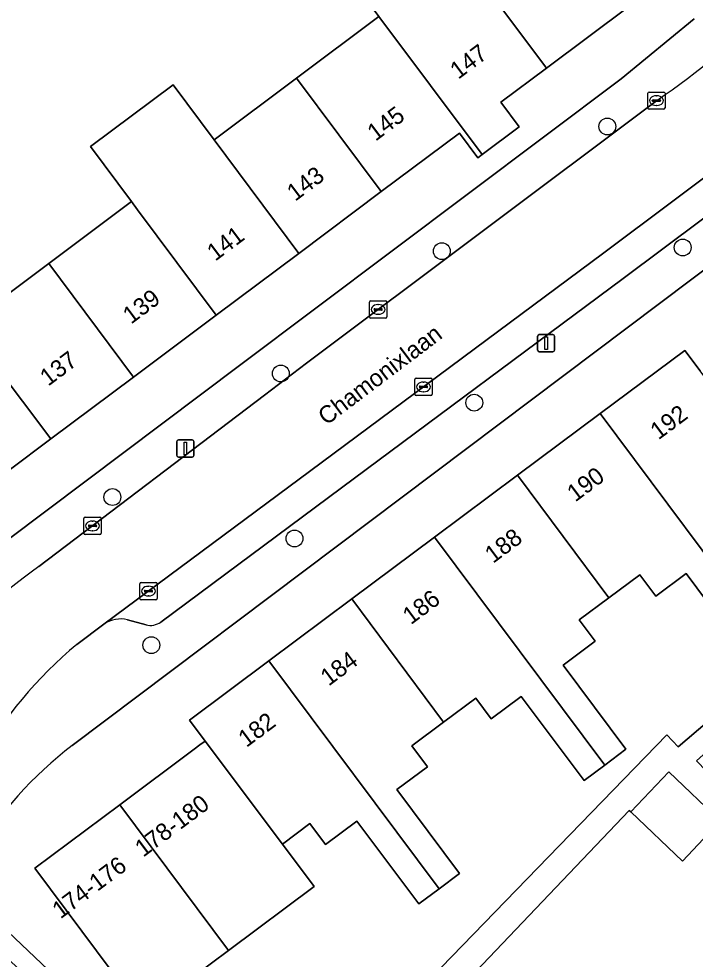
# Model space of a CAD drawing. Extents: x 158472 to 159562, y 388525 to 389606.
# Drawn here: x 159054.8 to 159094.1, y 388835.8 to 388890.5 of the extents above; entities that cross this region are included whole.
import ezdxf

# ---------------------------------------------------------------- set-up
doc = ezdxf.new("R2010")
doc.units = 0
for name, color, linetype in [('IMGEO_Boom', 7, 'Continuous'), ('IMGEO_Erf', 7, 'Continuous'), ('IMGEO_Kolk', 7, 'Continuous'), ('IMGEO_Lichtmast', 7, 'Continuous'), ('IMGEO_Openbare_ruimte_label', 7, 'Continuous'), ('IMGEO_Pand', 7, 'Continuous'), ('IMGEO_Pand_nummerreeks', 7, 'Continuous'), ('IMGEO_Parkeervlak_open', 7, 'Continuous'), ('IMGEO_Rijbaan_lokaal_open', 7, 'Continuous'), ('IMGEO_Voetpad_open', 7, 'Continuous')]:
    doc.layers.add(name, color=color, linetype=linetype)

msp = doc.modelspace()

# ---------------------------------------------------------------- linework, layer by layer
at = {"layer": 'IMGEO_Boom'}
for centre in [(159089.041, 388884.212), (159079.43, 388876.966), (159093.422, 388877.175), (159070.073, 388869.861), (159081.31, 388868.163), (159060.285, 388862.679), (159070.861, 388860.269), (159062.548, 388854.072)]:
    msp.add_circle(centre, 0.489, dxfattribs=at)
at = {"layer": 'IMGEO_Erf'}
for points in [[(159105.034, 388905.658), (159102.901, 388908.014), (159102.46, 388908.501), (159100.858, 388907.302), (159102.997, 388904.443), (159098.122, 388900.795), (159093.382, 388897.248), (159094.272, 388896.059), (159094.191, 388895.998), (159089.429, 388892.434), (159090.34, 388891.218), (159085.501, 388887.603), (159082.85, 388885.622), (159083.925, 388884.183), (159081.773, 388882.577), (159081.521, 388882.389), (159080.449, 388883.824), (159075.904, 388880.423), (159071.109, 388876.835), (159066.309, 388873.243), (159061.51, 388869.651), (159056.712, 388866.061), (159051.849, 388862.421)], [(159051.756, 388872.635), (159056.585, 388876.249), (159061.389, 388879.844), (159059.006, 388883.042), (159063.811, 388886.624), (159066.188, 388883.436), (159070.98, 388887.022), (159075.773, 388890.609), (159073.709, 388893.373)], [(159047.484, 388855.159), (159067.671, 388870.326), (159089.848, 388886.988), (159094.08, 388890.466)], [(159136.171, 388845.02), (159132.779, 388848.828), (159129.047, 388853.017), (159125.655, 388856.825), (159121.85, 388861.096), (159118.458, 388864.905), (159116.239, 388867.395), (159114.746, 388866.089), (159101.461, 388880.986), (159075.248, 388861.255), (159057.955, 388848.239)], [(159097.234, 388853.394), (159093.623, 388858.23), (159091.857, 388856.912), (159090.921, 388858.165), (159089.13, 388856.828), (159087.405, 388855.54), (159088.329, 388854.303), (159086.471, 388852.916), (159090.122, 388848.025), (159088.891, 388847.106), (159087.689, 388846.209), (159084.042, 388851.094), (159082.294, 388849.789), (159081.394, 388850.995), (159079.531, 388849.604), (159077.679, 388848.222), (159078.588, 388847.004), (159076.817, 388845.683), (159080.454, 388840.812), (159079.262, 388839.922), (159078.084, 388839.043), (159074.496, 388843.849), (159072.671, 388842.487), (159071.762, 388843.705), (159070.162, 388842.51), (159072, 388840.047), (159067.036, 388836.342), (159062.086, 388832.647), (159055.769, 388841.11), (159060.719, 388844.805), (159065.042, 388848.032), (159065.374, 388848.28), (159065.671, 388848.502), (159064.759, 388849.718), (159069.376, 388853.165), (159074.19, 388856.758), (159079.004, 388860.352), (159083.817, 388863.945), (159088.631, 388867.539), (159093.54, 388871.203), (159094.436, 388870.004)], [(159077.507, 388833.404), (159092.503, 388848.873), (159093.153, 388848.171), (159104.695, 388858.002)], [(159053.839, 388837.78), (159060.03, 388831.899)]]:
    msp.add_lwpolyline(points, dxfattribs=at)
msp.add_lwpolyline([(159105.403, 388834.476), (159103.483, 388836.282), (159101.286, 388833.958), (159098.241, 388836.836), (159095.321, 388839.596), (159097.518, 388841.921), (159095.549, 388843.782), (159093.409, 388841.532), (159090.402, 388844.391), (159090.316, 388844.473), (159079.843, 388833.493), (159083.846, 388829.656), (159087.76, 388825.904), (159091.675, 388822.152), (159095.589, 388818.4), (159099.59, 388814.565), (159112.182, 388827.882), (159111.226, 388828.786), (159109.085, 388826.521), (159106.088, 388829.354), (159103.169, 388832.113)], close=True, dxfattribs=at)
msp.add_arc((159070.589, 388831.351), 21.09, 126.8005, 150.2181, dxfattribs=at)
at = {"layer": 'IMGEO_Kolk'}
for p, q in [((159091.394, 388885.286), (159091.394, 388886.138)), ((159091.469, 388886.212), (159092.321, 388886.212)), ((159091.882, 388885.992), (159091.907, 388885.992)), ((159092.395, 388886.138), (159092.395, 388885.286)), ((159091.653, 388885.706), (159091.653, 388885.718)), ((159092.091, 388885.669), (159091.693, 388885.669)), ((159091.696, 388885.755), (159092.094, 388885.755)), ((159091.905, 388885.432), (159091.88, 388885.432)), ((159092.137, 388885.718), (159092.137, 388885.706)), ((159092.321, 388885.212), (159091.469, 388885.212)), ((159075.225, 388873.152), (159075.225, 388874.004)), ((159075.3, 388874.078), (159076.152, 388874.078)), ((159076.226, 388874.004), (159076.226, 388873.152)), ((159075.484, 388873.572), (159075.484, 388873.584)), ((159075.922, 388873.535), (159075.524, 388873.535)), ((159075.527, 388873.621), (159075.925, 388873.621)), ((159075.713, 388873.858), (159075.738, 388873.858)), ((159075.968, 388873.584), (159075.968, 388873.572)), ((159076.152, 388873.078), (159075.3, 388873.078)), ((159075.736, 388873.298), (159075.711, 388873.298)), ((159077.934, 388869.58), (159078.786, 388869.58)), ((159077.859, 388868.654), (159077.859, 388869.506)), ((159078.118, 388869.074), (159078.118, 388869.086)), ((159078.556, 388869.037), (159078.158, 388869.037)), ((159078.161, 388869.123), (159078.559, 388869.123)), ((159078.347, 388869.36), (159078.372, 388869.36)), ((159078.602, 388869.086), (159078.602, 388869.074)), ((159078.86, 388869.506), (159078.86, 388868.654)), ((159078.786, 388868.58), (159077.934, 388868.58)), ((159078.37, 388868.8), (159078.345, 388868.8)), ((159058.628, 388860.58), (159058.628, 388861.432)), ((159058.703, 388861.506), (159059.555, 388861.506)), ((159059.629, 388861.432), (159059.629, 388860.58)), ((159058.887, 388861), (159058.887, 388861.012)), ((159059.325, 388860.963), (159058.927, 388860.963)), ((159058.93, 388861.049), (159059.328, 388861.049)), ((159059.116, 388861.286), (159059.141, 388861.286)), ((159059.371, 388861.012), (159059.371, 388861)), ((159059.555, 388860.506), (159058.703, 388860.506)), ((159059.139, 388860.726), (159059.114, 388860.726)), ((159061.881, 388856.787), (159061.881, 388857.639)), ((159061.956, 388857.713), (159062.808, 388857.713)), ((159062.882, 388857.639), (159062.882, 388856.787)), ((159062.14, 388857.207), (159062.14, 388857.219)), ((159062.578, 388857.17), (159062.18, 388857.17)), ((159062.183, 388857.256), (159062.581, 388857.256)), ((159062.369, 388857.493), (159062.394, 388857.493)), ((159062.624, 388857.219), (159062.624, 388857.207)), ((159062.808, 388856.713), (159061.956, 388856.713)), ((159062.392, 388856.933), (159062.367, 388856.933))]:
    msp.add_line(p, q, dxfattribs=at)
for points in [[(159091.394, 388885.286), (159091.394, 388886.138)], [(159091.469, 388886.212), (159092.321, 388886.212)], [(159092.395, 388886.138), (159092.395, 388885.286)], [(159092.321, 388885.212), (159091.469, 388885.212)], [(159075.225, 388873.152), (159075.225, 388874.004)], [(159075.3, 388874.078), (159076.152, 388874.078)], [(159076.226, 388874.004), (159076.226, 388873.152)], [(159076.152, 388873.078), (159075.3, 388873.078)], [(159077.934, 388869.58), (159078.786, 388869.58)], [(159077.859, 388868.654), (159077.859, 388869.506)], [(159078.86, 388869.506), (159078.86, 388868.654)], [(159078.786, 388868.58), (159077.934, 388868.58)], [(159058.628, 388860.58), (159058.628, 388861.432)], [(159058.703, 388861.506), (159059.555, 388861.506)], [(159059.629, 388861.432), (159059.629, 388860.58)], [(159059.555, 388860.506), (159058.703, 388860.506)], [(159061.881, 388856.787), (159061.881, 388857.639)], [(159061.956, 388857.713), (159062.808, 388857.713)], [(159062.882, 388857.639), (159062.882, 388856.787)], [(159062.808, 388856.713), (159061.956, 388856.713)]]:
    msp.add_lwpolyline(points, dxfattribs=at)
for centre, radius, start, end in [((159091.471, 388886.136), 0.0765, 91.552, 178.448), ((159091.471, 388886.136), 0.0765, 91.552, 178.448), ((159092.319, 388886.136), 0.0765, 1.552, 88.448), ((159092.319, 388886.136), 0.0765, 1.552, 88.448), ((159091.693, 388885.715), 0.0403, 85.8775, 175.7526), ((159091.69, 388885.705), 0.0366, 178.938, 274.7102), ((159092.094, 388885.712), 0.043, 264.8664, 352.4533), ((159092.098, 388885.717), 0.0386, 1.7309, 96.639), ((159091.471, 388885.288), 0.0765, 181.552, 268.448), ((159091.471, 388885.288), 0.0765, 181.552, 268.448), ((159092.319, 388885.288), 0.0765, 271.552, 358.448), ((159092.319, 388885.288), 0.0765, 271.552, 358.448), ((159075.302, 388874.002), 0.0765, 91.552, 178.448), ((159075.302, 388874.002), 0.0765, 91.552, 178.448), ((159076.15, 388874.002), 0.0765, 1.552, 88.448), ((159076.15, 388874.002), 0.0765, 1.552, 88.448), ((159075.524, 388873.581), 0.0403, 85.8775, 175.7526), ((159075.521, 388873.571), 0.0366, 178.938, 274.7102), ((159075.925, 388873.578), 0.043, 264.8664, 352.4533), ((159075.929, 388873.583), 0.0386, 1.7309, 96.639), ((159075.302, 388873.154), 0.0765, 181.552, 268.448), ((159075.302, 388873.154), 0.0765, 181.552, 268.448), ((159076.15, 388873.154), 0.0765, 271.552, 358.448), ((159076.15, 388873.154), 0.0765, 271.552, 358.448), ((159077.936, 388869.504), 0.0765, 91.552, 178.448), ((159077.936, 388869.504), 0.0765, 91.552, 178.448), ((159078.784, 388869.504), 0.0765, 1.552, 88.448), ((159078.784, 388869.504), 0.0765, 1.552, 88.448), ((159078.158, 388869.083), 0.0403, 85.8775, 175.7526), ((159078.155, 388869.073), 0.0366, 178.938, 274.7102), ((159078.559, 388869.08), 0.043, 264.8664, 352.4533), ((159078.563, 388869.085), 0.0386, 1.7309, 96.639), ((159077.936, 388868.656), 0.0765, 181.552, 268.448), ((159077.936, 388868.656), 0.0765, 181.552, 268.448), ((159078.784, 388868.656), 0.0765, 271.552, 358.448), ((159078.784, 388868.656), 0.0765, 271.552, 358.448), ((159058.705, 388861.43), 0.0765, 91.552, 178.448), ((159058.705, 388861.43), 0.0765, 91.552, 178.448), ((159059.553, 388861.43), 0.0765, 1.552, 88.448), ((159059.553, 388861.43), 0.0765, 1.552, 88.448), ((159058.927, 388861.009), 0.0403, 85.8775, 175.7526), ((159058.924, 388860.999), 0.0366, 178.938, 274.7102), ((159059.328, 388861.006), 0.043, 264.8664, 352.4533), ((159059.332, 388861.011), 0.0386, 1.7309, 96.639), ((159058.705, 388860.582), 0.0765, 181.552, 268.448), ((159058.705, 388860.582), 0.0765, 181.552, 268.448), ((159059.553, 388860.582), 0.0765, 271.552, 358.448), ((159059.553, 388860.582), 0.0765, 271.552, 358.448), ((159061.958, 388857.637), 0.0765, 91.552, 178.448), ((159061.958, 388857.637), 0.0765, 91.552, 178.448), ((159062.806, 388857.637), 0.0765, 1.552, 88.448), ((159062.806, 388857.637), 0.0765, 1.552, 88.448), ((159062.18, 388857.216), 0.0403, 85.8775, 175.7526), ((159062.177, 388857.206), 0.0366, 178.938, 274.7102), ((159062.581, 388857.213), 0.043, 264.8664, 352.4533), ((159062.585, 388857.218), 0.0386, 1.7309, 96.639), ((159061.958, 388856.789), 0.0765, 181.552, 268.448), ((159061.958, 388856.789), 0.0765, 181.552, 268.448), ((159062.806, 388856.789), 0.0765, 271.552, 358.448), ((159062.806, 388856.789), 0.0765, 271.552, 358.448)]:
    msp.add_arc(centre, radius, start, end, dxfattribs=at)
for centre, major_axis, ratio, start_param, end_param in [((159091.881, 388885.712), (-0.387, 0.002), 0.722429, 4.712389, 7.853982), ((159091.906, 388885.712), (-0.39, 0.002), 0.717154, 1.570796, 4.712389), ((159075.712, 388873.578), (-0.387, 0.002), 0.722429, 4.712389, 7.853982), ((159075.737, 388873.578), (-0.39, 0.002), 0.717154, 1.570796, 4.712389), ((159078.346, 388869.08), (-0.387, 0.002), 0.722429, 4.712389, 7.853982), ((159078.371, 388869.08), (-0.39, 0.002), 0.717154, 1.570796, 4.712389), ((159059.115, 388861.006), (-0.387, 0.002), 0.722429, 4.712389, 7.853982), ((159059.14, 388861.006), (-0.39, 0.002), 0.717154, 1.570796, 4.712389), ((159062.368, 388857.213), (-0.387, 0.002), 0.722429, 4.712389, 7.853982), ((159062.393, 388857.213), (-0.39, 0.002), 0.717154, 1.570796, 4.712389)]:
    msp.add_ellipse(centre, major_axis=major_axis, ratio=ratio, start_param=start_param, end_param=end_param, dxfattribs=at)
at = {"layer": 'IMGEO_Lichtmast'}
for p, q in [((159084.988, 388871.22), (159084.988, 388872.02)), ((159084.988, 388872.02), (159084.988, 388871.22)), ((159085.088, 388872.12), (159085.878, 388872.12)), ((159085.878, 388872.12), (159085.088, 388872.12)), ((159085.978, 388872.02), (159085.978, 388871.22)), ((159085.978, 388871.22), (159085.978, 388872.02)), ((159085.878, 388871.12), (159085.088, 388871.12)), ((159085.088, 388871.12), (159085.878, 388871.12)), ((159064.027, 388865.101), (159064.027, 388865.901)), ((159064.027, 388865.901), (159064.027, 388865.101)), ((159064.127, 388866.001), (159064.917, 388866.001)), ((159064.917, 388866.001), (159064.127, 388866.001)), ((159065.017, 388865.901), (159065.017, 388865.101)), ((159065.017, 388865.101), (159065.017, 388865.901)), ((159064.917, 388865.001), (159064.127, 388865.001)), ((159064.127, 388865.001), (159064.917, 388865.001))]:
    msp.add_line(p, q, dxfattribs=at)
for points in [[(159085.408, 388871.995), (159085.558, 388871.995), (159085.558, 388871.245), (159085.408, 388871.245), (159085.408, 388871.995)], [(159064.447, 388865.876), (159064.597, 388865.876), (159064.597, 388865.126), (159064.447, 388865.126), (159064.447, 388865.876)]]:
    msp.add_lwpolyline(points, dxfattribs=at)
for centre, start, end in [((159085.088, 388872.02), 90, 180), ((159085.088, 388872.02), 90, 180), ((159085.878, 388872.02), 0, 90), ((159085.878, 388872.02), 360, 90), ((159085.088, 388871.22), 180, 270), ((159085.088, 388871.22), 180, 270), ((159085.878, 388871.22), 270, 0), ((159085.878, 388871.22), 270, 0), ((159064.127, 388865.901), 90, 180), ((159064.127, 388865.901), 90, 180), ((159064.917, 388865.901), 0, 90), ((159064.917, 388865.901), 360, 90), ((159064.127, 388865.101), 180, 270), ((159064.127, 388865.101), 180, 270), ((159064.917, 388865.101), 270, 0), ((159064.917, 388865.101), 270, 0)]:
    msp.add_arc(centre, 0.1, start, end, dxfattribs=at)
at = {"layer": 'IMGEO_Pand'}
for points in [[(159082.584, 388901.51), (159079.742, 388899.383), (159081.58, 388896.941), (159079.623, 388895.476), (159085.501, 388887.603), (159090.34, 388891.218), (159089.429, 388892.434), (159084.422, 388899.068)], [(159081.773, 388882.577), (159083.925, 388884.183), (159082.85, 388885.622), (159085.501, 388887.603), (159079.623, 388895.476), (159079.398, 388895.308), (159078.284, 388896.796), (159073.709, 388893.373), (159075.773, 388890.609)], [(159081.773, 388882.577), (159075.773, 388890.609), (159070.98, 388887.022), (159075.904, 388880.423), (159080.449, 388883.824), (159081.521, 388882.389)], [(159066.188, 388883.436), (159063.811, 388886.624), (159059.006, 388883.042), (159061.389, 388879.844), (159061.744, 388879.368), (159066.309, 388873.243), (159071.109, 388876.835)], [(159071.109, 388876.835), (159075.904, 388880.423), (159070.98, 388887.022), (159066.188, 388883.436)], [(159061.389, 388879.844), (159056.585, 388876.249), (159061.51, 388869.651), (159066.309, 388873.243), (159061.744, 388879.368)], [(159051.849, 388862.421), (159056.712, 388866.061), (159051.756, 388872.635), (159050.766, 388873.917), (159048.406, 388877.097), (159043.307, 388873.28), (159045.14, 388871.51), (159046.01, 388870.3)], [(159061.51, 388869.651), (159056.585, 388876.249), (159051.756, 388872.635), (159056.712, 388866.061)], [(159088.631, 388867.539), (159098.49, 388854.332), (159099.71, 388855.242), (159096.126, 388860.044), (159097.901, 388861.369), (159096.986, 388862.595), (159098.9, 388864.024), (159094.436, 388870.004), (159093.54, 388871.203)], [(159089.13, 388856.828), (159090.921, 388858.165), (159091.857, 388856.912), (159093.623, 388858.23), (159097.234, 388853.394), (159098.49, 388854.332), (159088.631, 388867.539), (159083.817, 388863.945)], [(159079.004, 388860.352), (159088.891, 388847.106), (159090.122, 388848.025), (159086.471, 388852.916), (159088.329, 388854.303), (159087.405, 388855.54), (159089.13, 388856.828), (159083.817, 388863.945)], [(159079.004, 388860.352), (159074.19, 388856.758), (159079.531, 388849.604), (159081.394, 388850.995), (159082.294, 388849.789), (159084.042, 388851.094), (159087.689, 388846.209), (159088.891, 388847.106)], [(159069.376, 388853.165), (159079.262, 388839.922), (159080.454, 388840.812), (159076.817, 388845.683), (159078.588, 388847.004), (159077.679, 388848.222), (159079.531, 388849.604), (159074.19, 388856.758)], [(159069.376, 388853.165), (159064.759, 388849.718), (159065.671, 388848.502), (159070.162, 388842.51), (159071.762, 388843.705), (159072.671, 388842.487), (159074.496, 388843.849), (159078.084, 388839.043), (159079.262, 388839.922)], [(159065.671, 388848.502), (159065.374, 388848.28), (159065.042, 388848.032), (159060.719, 388844.805), (159067.036, 388836.342), (159072, 388840.047), (159070.162, 388842.51)], [(159090.402, 388844.391), (159093.409, 388841.532), (159095.549, 388843.782), (159095.614, 388843.85), (159092.606, 388846.71)], [(159060.719, 388844.805), (159055.769, 388841.11), (159062.086, 388832.647), (159067.036, 388836.342)]]:
    msp.add_lwpolyline(points, close=True, dxfattribs=at)
at = {"layer": 'IMGEO_Parkeervlak_open'}
for points in [[(159097.916, 388883.688), (159096.865, 388882.864), (159088.845, 388876.87), (159072.405, 388864.659), (159059.794, 388855.292)], [(159063.098, 388855.419), (159073.604, 388863.223), (159089.961, 388875.372), (159096.885, 388880.547)], [(159061.171, 388855.55), (159062.237, 388855.258)]]:
    msp.add_lwpolyline(points, dxfattribs=at)
for centre, radius, start, end in [((159060.767, 388853.904), 1.695, 76.2017, 125.0225), ((159062.503, 388856.22), 0.998, 254.5682, 306.6148)]:
    msp.add_arc(centre, radius, start, end, dxfattribs=at)
at = {"layer": 'IMGEO_Rijbaan_lokaal_open'}
for points in [[(159058.218, 388854.121), (159059.794, 388855.292), (159072.405, 388864.659), (159088.845, 388876.87), (159096.865, 388882.864), (159097.916, 388883.688), (159101.42, 388886.701)], [(159091.893, 388885.708), (159071.563, 388870.451), (159069.118, 388868.593), (159056.018, 388858.639)]]:
    msp.add_lwpolyline(points, dxfattribs=at)
for centre, radius, start, end in [((159070.95, 388916.944), 37.607, 303.8405, 330.852), ((159074.227, 388832.759), 31.644, 125.1302, 141.4165), ((159073.327, 388835.819), 23.733, 129.5419, 151.3006)]:
    msp.add_arc(centre, radius, start, end, dxfattribs=at)
at = {"layer": 'IMGEO_Voetpad_open'}
for points in [[(159094.08, 388890.466), (159089.848, 388886.988), (159067.671, 388870.326), (159047.484, 388855.159), (159046.611, 388854.503), (159046.143, 388854.918), (159044.684, 388853.597), (159041.757, 388850.948), (159040.611, 388849.91), (159043.009, 388847.412), (159042.094, 388846.371), (159034.383, 388837.602), (159004.229, 388805.879), (159005.956, 388804.315), (159007.95, 388802.429), (159009.905, 388799.335)], [(159056.018, 388858.639), (159069.118, 388868.593), (159071.563, 388870.451), (159091.893, 388885.708)], [(159057.955, 388848.239), (159075.248, 388861.255), (159101.461, 388880.986), (159114.746, 388866.089), (159116.239, 388867.395), (159118.458, 388864.905), (159121.85, 388861.096), (159125.655, 388856.825), (159129.047, 388853.017), (159132.779, 388848.828), (159136.171, 388845.02), (159145.569, 388834.47), (159147.838, 388836.491), (159129.752, 388856.818), (159116.489, 388871.743), (159113.174, 388868.76), (159102.05, 388881.339), (159096.885, 388880.547), (159089.961, 388875.372), (159073.604, 388863.223), (159063.098, 388855.419)], [(159109.241, 388832.951), (159106.097, 388835.939), (159103.201, 388838.691), (159101.443, 388840.396), (159098.238, 388843.442), (159095.369, 388846.169), (159094.214, 388847.35), (159105.322, 388857.302), (159104.993, 388857.67), (159104.695, 388858.002), (159093.153, 388848.171), (159092.503, 388848.873), (159077.507, 388833.404)], [(159062.237, 388855.258), (159061.171, 388855.55)], [(159059.794, 388855.292), (159058.218, 388854.121)], [(159079.843, 388833.493), (159090.316, 388844.473), (159090.402, 388844.391), (159092.606, 388846.71), (159095.614, 388843.85), (159095.549, 388843.782), (159097.518, 388841.921), (159097.562, 388841.967), (159100.499, 388839.191), (159103.527, 388836.329), (159103.483, 388836.282), (159105.403, 388834.476)]]:
    msp.add_lwpolyline(points, dxfattribs=at)
msp.add_lwpolyline([(159069.331, 388822.993), (159070.217, 388823.817), (159069.34, 388824.689), (159067.15, 388826.811), (159066.36, 388825.887), (159060.03, 388831.899), (159053.839, 388837.78), (159053.046, 388836.945), (159066.136, 388824.477), (159064.812, 388823.162), (159071.406, 388816.83), (159072.24, 388816.029), (159079.028, 388809.511), (159079.885, 388808.688), (159086.411, 388802.422), (159087.242, 388801.624), (159087.648, 388801.234), (159089.681, 388803.339), (159089.222, 388803.782)], close=True, dxfattribs=at)
for centre, radius, start, end in [((159070.95, 388916.944), 37.607, 303.8405, 330.852), ((159074.227, 388832.759), 31.644, 125.1302, 141.4165), ((159060.767, 388853.904), 1.695, 76.2017, 125.0225), ((159062.503, 388856.22), 0.998, 254.5682, 306.6148), ((159073.327, 388835.819), 23.733, 129.5419, 151.3006), ((159070.589, 388831.351), 21.09, 126.8005, 150.2181)]:
    msp.add_arc(centre, radius, start, end, dxfattribs=at)

# ---------------------------------------------------------------- texts
at = {"layer": 'IMGEO_Openbare_ruimte_label'}
msp.add_text('Chamonixlaan', height=1, rotation=37.0761, dxfattribs=at).set_placement((159072.715, 388866.813))
at = {"layer": 'IMGEO_Pand_nummerreeks'}
for s, rotation, p in [('147', 36.7799, (159080.382, 388886.92)), ('145', 36.8089, (159075.573, 388883.322)), ('143', 36.8089, (159070.903, 388879.828)), ('141', 36.8068, (159066.26, 388876.354)), ('139', 36.8068, (159061.369, 388872.694)), ('137', 36.8089, (159056.554, 388869.09)), ('192', 36.7371, (159092.014, 388865.971)), ('190', 36.7422, (159087.178, 388862.36)), ('188', 36.7422, (159082.403, 388858.796)), ('186', 36.7422, (159077.626, 388855.23)), ('184', 36.7422, (159072.851, 388851.665)), ('182', 36.7438, (159068.075, 388848.101)), ('178-180', 36.7438, (159062.073, 388841.722)), ('174-176', 36.74, (159057.268, 388838.136))]:
    msp.add_text(s, height=1, rotation=rotation, dxfattribs=at).set_placement(p)

doc.saveas('drawing.dxf')
